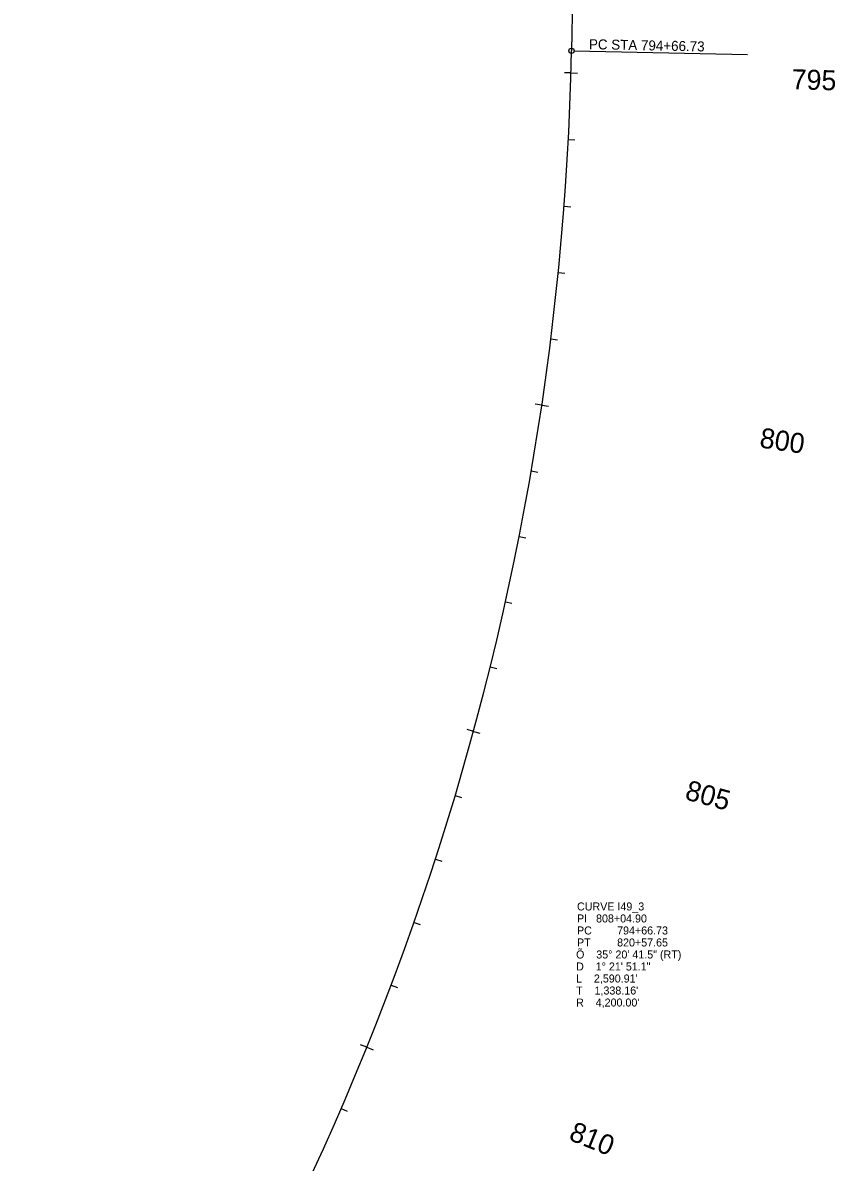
# Model space of a CAD drawing. Extents: x 2819977 to 2827606, y 116785 to 150320.
# Drawn here: x 2822878 to 2824096, y 137743 to 139451 of the extents above; entities that cross this region are included whole.
import ezdxf

# ---------------------------------------------------------------- set-up
doc = ezdxf.new("R2010")
doc.units = 0
for name, color, linetype in [('Default', 7, 'Continuous'), ('Roadway-Centerline main', 7, 'Continuous'), ('Roadway-Curve pc pt', 7, 'Continuous'), ('Text-Curve info', 7, 'Continuous')]:
    doc.layers.add(name, color=color, linetype=linetype)

msp = doc.modelspace()

# ---------------------------------------------------------------- linework, layer by layer
at = {"layer": 'Default'}
msp.add_arc((2819501.9, 139492.9), 4200, 323.5041, 358.849, dxfattribs=at)
at = {"layer": 'Roadway-Centerline main'}
for p, q in [((2823760.8, 142380.9), (2823701.1, 139408.5)), ((2823700.3, 139375.3), (2823690.3, 139375.6)), ((2823700.3, 139375.3), (2823710.2, 139375)), ((2823696.3, 139275.4), (2823706.2, 139274.9)), ((2823689.9, 139175.6), (2823699.9, 139174.8)), ((2823681.2, 139076), (2823691.1, 139075)), ((2823670, 138976.6), (2823680, 138975.4)), ((2823656.6, 138877.5), (2823646.7, 138879)), ((2823656.6, 138877.5), (2823666.5, 138876)), ((2823640.7, 138778.8), (2823650.6, 138777.1)), ((2823622.6, 138680.4), (2823632.4, 138678.5)), ((2823602.1, 138582.6), (2823611.8, 138580.4)), ((2823579.2, 138485.2), (2823588.9, 138482.8)), ((2823554.1, 138388.4), (2823544.4, 138391)), ((2823554.1, 138388.4), (2823563.7, 138385.8)), ((2823526.6, 138292.3), (2823536.2, 138289.4)), ((2823496.9, 138196.8), (2823506.4, 138193.7)), ((2823464.9, 138102), (2823474.3, 138098.7)), ((2823430.7, 138008.1), (2823440, 138004.5)), ((2823394.2, 137915), (2823384.9, 137918.7)), ((2823394.2, 137915), (2823403.5, 137911.2)), ((2823355.5, 137822.8), (2823364.7, 137818.8))]:
    msp.add_line(p, q, dxfattribs=at)
msp.add_arc((2819501.9, 139492.9), 4200, 323.5041, 358.849, dxfattribs=at)
at = {"layer": 'Roadway-Curve pc pt'}
msp.add_line((2823705.1, 139408.5), (2823964.7, 139403.2), dxfattribs=at)
msp.add_circle((2823701.1, 139408.5), 4, dxfattribs=at)

# ---------------------------------------------------------------- texts
at = {"layer": 'Roadway-Centerline main'}
for s, rotation, p in [(' 795', 358.3951, (2824019.7, 139351.3)), (' 800', 351.5742, (2823970.9, 138815.8)), (' 805', 344.7533, (2823858.9, 138289.8)), (' 810', 337.9324, (2823685.1, 137780.8))]:
    msp.add_text(s, height=30, rotation=rotation, dxfattribs=at).set_placement(p)
at = {"layer": 'Roadway-Curve pc pt'}
msp.add_text('PC STA 794+66.73', height=15, rotation=358.849, dxfattribs=at).set_placement((2823727.1, 139411))
at = {"layer": 'Text-Curve info'}
for s, p in [('CURVE I49_3', (2823709.3, 138119.9)), ('PI   808+04.90', (2823709.3, 138101.9)), ('PC', (2823709.3, 138083.9)), ('794+66.73', (2823769.4, 138083.9)), ('PT', (2823709.3, 138065.9)), ('820+57.65', (2823769.4, 138065.9)), ('Õ    35%%d 20\' 41.5" (RT)', (2823707.9, 138047.9)), ('D    1%%d 21\' 51.1"', (2823707.9, 138029.9)), ("L    2,590.91'", (2823707.9, 138011.9)), ("T    1,338.16'", (2823707.9, 137993.9)), ("R    4,200.00'", (2823707.9, 137975.9))]:
    msp.add_text(s, height=12, dxfattribs=at).set_placement(p)

doc.saveas('drawing.dxf')
